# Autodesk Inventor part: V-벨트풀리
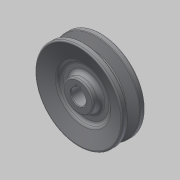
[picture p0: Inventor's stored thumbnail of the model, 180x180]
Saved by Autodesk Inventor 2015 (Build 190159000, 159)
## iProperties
Created: 2016-08
Part Number: V-벨트풀리
Material: 알루미늄 6061
Document SubType Name: Modeling
Designer: mduedu
Density: 2.71 g/cm^3
Appearance: 기본값
Author: mduedu
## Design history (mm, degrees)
sketch "스케치1"
  geometry: L1 (0, 9.5)-(0, -9.5); L2 (0, 9.5)-(35, 9.5); L3 (35, 9.5)-(35, 4.825); L4 (35, 4.825)-(26, 2.074); L5 (26, 2.074)-(26, 0); L6 (0, 0)-(26, 0); L7 (0, -9.5)-(35, -9.5); L8 (35, -9.5)-(35, -4.825); L9 (35, -4.825)-(26, -2.074); L10 (26, -2.074)-(26, 0); L11 (32.3, 9.5)-(32.3, -9.5); 3 further points
  constraints: 22 end point, 6 point on line, 4 perpendicular, 3 symmetric about line, 1 coincident, 1 horizontal alignment, 1 midpoint, 1 parallel, 1 vertical
  dimensions: "d0" = 19 distance of L1.start L1.end; "d2" = 70 diameter of L8 L1; "d4" = 6.3 distance between parallel lines of L10 L11; "d5" = 2.7 distance between parallel lines of L11 L8; "d6" = 8 distance of point (32.3, -4) point (32.3, 4); "d7" = 34 deg angle of L9 L4
revolve "회전1" sketch "스케치1" stored, may be unused: angle "d8" = 90 deg
sketch "스케치2"
  geometry: L1 (-2, 0)-(2, 0); L2 (2, 0)-(2, 7.8); L3 (2, 7.8)-(-2, 7.8); L4 (-2, 7.8)-(-2, 0); C1 r 6 at (0, 0); 2 further points
  constraints: 8 end point, 2 coincident, 2 parallel, 1 centre point, 1 horizontal, 1 midpoint, 1 perpendicular
  dimensions: "d9" = 12 diameter of C1; "d11" = 4 distance of L2.end L3.end; "d12" = 7.8 distance of L1.end L2.end
extrude "돌출1" cut sketch "스케치2" stored distance "d13" = 10; taper "d14" = 0 deg
sketch "스케치3"
  geometry: L1 (35, 4.825)-(26, 2.074) reference; L2 (26, 2.074)-(26, -2.074) reference; L3 (0, 0)-(26, 0); L4 (35, 9.5)-(35, 4.825) reference; L5 (-35, 9.5)-(35, 9.5) reference; L6 (35, 9.5)-(21, 5.22); L7 (21, 5.22)-(21, 3); L8 (21, 3)-(12, 3); L9 (12, 3)-(12, 9.5); L10 (0, 9.5)-(0, -9.5); L11 (5.657, -9.5)-(-6, -9.5) reference; L12 (12, 9.5)-(35, 9.5)
  constraints: 14 end point, 3 midpoint, 2 parallel, 2 perpendicular, 2 point on line, 1 collinear, 1 horizontal
  dimensions: "d15" = 3 distance between parallel lines of L3 L8; "d17" = 42 diameter of L7 L10; "d18" = 24 diameter of L9 L10
revolve "회전2" sketch "스케치3" stored, may be unused: angle "d19" = 90 deg
fillet "모깎기1" dims "d20" = 0.5, "d21" = 1, "d22" = 1
fillet "모깎기2" dims "d23" = 3
fillet "모깎기3" dims "d24" = 3
fillet "모깎기4" dims "d25" = 3
chamfer "모따기1" distance "d26" = 0.5; stored, may be unused: second distance "d27" = 2, angle "d28" = 45 deg
fillet "모깎기5" dims "d29" = 1
node "솔리드1"
mirror "대칭1"
